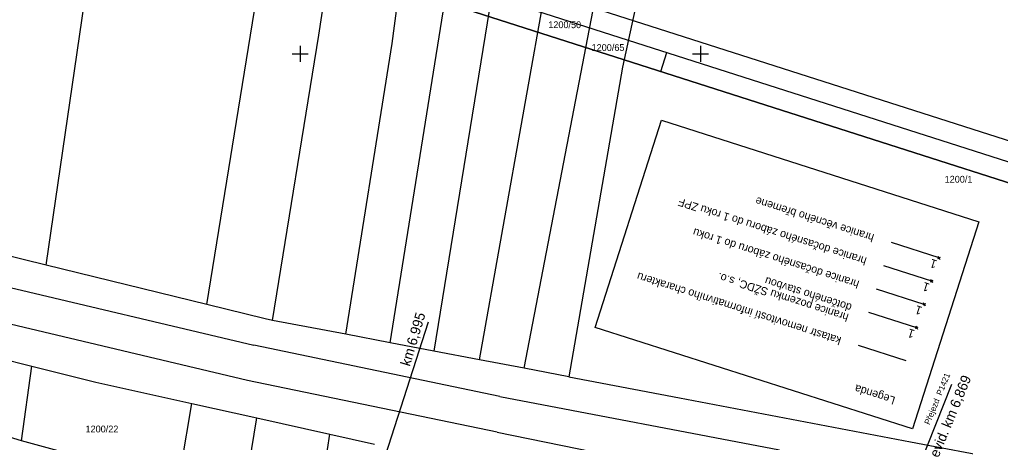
# Model space of a CAD drawing. Extents: x -779302 to -774398, y -1144902 to -1142831.
# Drawn here: x -777170.1 to -776925.1, y -1143797.2 to -1143691.5 of the extents above; entities that cross this region are included whole.
import ezdxf

# ---------------------------------------------------------------- set-up
doc = ezdxf.new("R2010")
doc.units = 0
for name, color, linetype in [('hektosit - Vrstva 5', 7, 'Continuous'), ('Hranice parcel', 7, 'Continuous'), ('legenda - Vrstva 7', 7, 'Continuous'), ('legenda I_5_2 - Vrstva 3', 7, 'Continuous'), ('Parcelní čísla', 7, 'Continuous'), ('Vnitřní kresba', 7, 'Continuous'), ('Vrstva 1', 7, 'Continuous'), ('zjednodus_g_situ-seda - Vrstva 4', 7, 'Continuous'), ('zjednodus_g_situ-seda - Vrstva 9', 7, 'Continuous')]:
    doc.layers.add(name, color=color, linetype=linetype)

msp = doc.modelspace()

# ---------------------------------------------------------------- linework, layer by layer
at = {"layer": 'hektosit - Vrstva 5'}
for p, q in [((-777102, -1143700), (-777098, -1143700)), ((-777100, -1143698), (-777100, -1143702)), ((-777002, -1143700), (-776998, -1143700)), ((-777000, -1143698), (-777000, -1143702))]:
    msp.add_line(p, q, dxfattribs=at)
at = {"layer": 'Hranice parcel'}
for p, q in [((-777163.47, -1143752.88), (-777183.19, -1143748.04)), ((-777123.33, -1143762.74), (-777163.47, -1143752.88)), ((-777088.61, -1143770.15), (-777106.91, -1143766.67)), ((-777077.49, -1143772.27), (-777088.61, -1143770.15)), ((-777187.43, -1143773.05), (-777167.09, -1143778.12)), ((-777066.64, -1143774.34), (-777077.49, -1143772.27)), ((-777055.19, -1143776.52), (-777066.64, -1143774.34)), ((-777169.67, -1143796.75), (-777167.09, -1143778.12)), ((-777044.03, -1143778.64), (-777055.19, -1143776.52)), ((-777032.87, -1143780.76), (-777044.03, -1143778.64)), ((-777130.46, -1143807.42), (-777127.12, -1143787.44)), ((-777127.12, -1143787.44), (-777110.85, -1143791.06)), ((-777169.67, -1143796.75), (-777190.45, -1143790.44)), ((-777114.23, -1143811.91), (-777110.85, -1143791.06)), ((-777110.85, -1143791.06), (-777092.58, -1143795.13)), ((-777096.09, -1143818.07), (-777092.58, -1143795.13)), ((-777092.58, -1143795.13), (-777081.42, -1143797.61)), ((-777130.46, -1143807.42), (-777169.67, -1143796.75))]:
    msp.add_line(p, q, dxfattribs=at)
for points in [[(-777123.33, -1143762.74), (-777110.9, -1143686.03), (-777093.45, -1143555.1)], [(-777106.91, -1143766.67), (-777095.36, -1143695.37), (-777073.85, -1143554.22)], [(-777163.47, -1143752.88), (-777139.64, -1143589.33), (-777135.82, -1143560)], [(-777088.61, -1143770.15), (-777077.04, -1143697.42), (-777068.9, -1143635.62), (-777059.73, -1143583.76), (-777054.08, -1143557.98)], [(-777077.49, -1143772.27), (-777044.61, -1143566.63), (-777044.04, -1143563.26)], [(-777033.04, -1143573.27), (-777033.93, -1143577.36), (-777047.95, -1143659.41), (-777066.64, -1143774.34)], [(-777055.19, -1143776.52), (-777021.75, -1143588.42), (-777021.1, -1143583.96)], [(-777044.03, -1143778.64), (-777025.1, -1143680.27), (-777016.92, -1143640), (-777009.52, -1143599.22), (-777008.49, -1143594.9)], [(-776994.01, -1143610.04), (-777008.23, -1143651.46), (-777019.5, -1143703.38), (-777032.87, -1143780.76)], [(-777106.91, -1143766.67), (-777108.78, -1143766.31), (-777123.33, -1143762.74)], [(-777167.09, -1143778.12), (-777151.05, -1143782.11), (-777127.12, -1143787.44)], [(-777032.87, -1143780.76), (-777005.26, -1143786.02), (-776947.51, -1143797.01), (-776924.63, -1143801.37), (-776885.75, -1143807.75)]]:
    msp.add_lwpolyline(points, dxfattribs=at)
at = {"layer": 'legenda - Vrstva 7'}
msp.add_lwpolyline([(-776947, -1143793.82), (-777026.29, -1143768.44), (-777009.71, -1143716.63), (-776930.42, -1143742.01)], close=True, dxfattribs=at)
at = {"layer": 'legenda I_5_2 - Vrstva 3'}
for p, q in [((-776940.36, -1143751.05), (-776952.3, -1143747.23)), ((-776940.1, -1143750.92), (-776940.73, -1143751.25)), ((-776940.61, -1143751.18), (-776939.98, -1143750.86)), ((-776940.23, -1143751.3), (-776940.55, -1143750.68)), ((-776940.48, -1143750.8), (-776940.16, -1143751.43)), ((-776940.36, -1143751.05), (-776940.36, -1143751.05)), ((-776942.22, -1143756.87), (-776954.16, -1143753.04)), ((-776944.08, -1143762.68), (-776956.03, -1143758.86)), ((-776941.96, -1143756.74), (-776942.59, -1143757.06)), ((-776942.47, -1143757), (-776941.84, -1143756.67)), ((-776942.09, -1143757.12), (-776942.41, -1143756.49)), ((-776942.35, -1143756.62), (-776942.02, -1143757.24)), ((-776942.22, -1143756.87), (-776942.22, -1143756.87)), ((-776943.83, -1143762.55), (-776944.45, -1143762.88)), ((-776944.33, -1143762.81), (-776943.7, -1143762.49)), ((-776943.95, -1143762.93), (-776944.27, -1143762.3)), ((-776944.21, -1143762.43), (-776943.88, -1143763.06)), ((-776944.08, -1143762.68), (-776944.08, -1143762.68)), ((-776945.94, -1143768.5), (-776957.89, -1143764.67)), ((-776945.69, -1143768.37), (-776946.31, -1143768.69)), ((-776946.19, -1143768.62), (-776945.56, -1143768.3)), ((-776945.81, -1143768.75), (-776946.13, -1143768.12)), ((-776946.07, -1143768.24), (-776945.74, -1143768.87)), ((-776945.94, -1143768.5), (-776945.94, -1143768.5)), ((-776948.59, -1143776.77), (-776960.54, -1143772.95))]:
    msp.add_line(p, q, dxfattribs=at)
at = {"layer": 'Vnitřní kresba'}
for p, q in [((-777312.68, -1143725.18), (-777111.56, -1143772.88)), ((-777113.15, -1143781.74), (-777316.11, -1143733.54)), ((-777050.15, -1143785.67), (-777111.56, -1143772.88)), ((-777050.79, -1143794.65), (-777113.15, -1143781.74)), ((-777050.15, -1143785.67), (-776980.28, -1143799.08)), ((-777050.79, -1143794.65), (-776981.09, -1143808.78))]:
    msp.add_line(p, q, dxfattribs=at)
at = {"layer": 'Vrstva 1'}
msp.add_line((-777009.93, -1143704.44), (-777008.41, -1143699.68), dxfattribs=at)
for points in [[(-776606.88, -1143822.95), (-777806.9, -1143438.86), (-777897.43, -1143721.71), (-776697.42, -1144105.81)], [(-776700.65, -1144099.52), (-777891.15, -1143718.47), (-777803.66, -1143445.14), (-776613.17, -1143826.19)], [(-776619.45, -1143829.42), (-777605.19, -1143513.91), (-777689.63, -1143777.73), (-776703.89, -1144093.24)], [(-776703.89, -1144093.24), (-777689.63, -1143777.73), (-777605.19, -1143513.91), (-776619.45, -1143829.42)]]:
    msp.add_lwpolyline(points, close=True, dxfattribs=at)
at = {"layer": 'zjednodus_g_situ-seda - Vrstva 4'}
msp.add_line((-776971.31, -1143868.72), (-776937.22, -1143782.62), dxfattribs=at)
at = {"layer": 'zjednodus_g_situ-seda - Vrstva 9'}
msp.add_line((-777086.17, -1143823.78), (-777067.91, -1143767.04), dxfattribs=at)

# ---------------------------------------------------------------- texts
at = {"layer": 'legenda I_5_2 - Vrstva 3'}
for s, height, p in [('hranice dočasného záboru do 1 roku ZPF', 2, (-776958.3, -1143751.03)), ('hranice věcného břemene', 2, (-776956.44, -1143745.21)), ('hranice dočasného záboru do 1 roku', 2, (-776960.16, -1143756.84)), ('1', 2.16, (-776940.7, -1143751.75)), ('katastr nemovitostí informativního charakteru', 2, (-776964.67, -1143770.93)), ('hranice pozemku SŽDC, s.o.', 2, (-776962.81, -1143765.12)), ('dotčeného stavbou', 2, (-776962.02, -1143762.66)), ('1', 2.16, (-776942.56, -1143757.56)), ('1', 2.16, (-776944.42, -1143763.38)), ('1', 2.16, (-776946.28, -1143769.19)), ('Legenda', 2, (-776951.17, -1143785.88))]:
    msp.add_text(s, height=height, rotation=162.2529, dxfattribs=at).set_placement(p)
at = {"layer": 'Parcelní čísla'}
for s, p in [('1200/50', (-777038.03, -1143693.62)), ('1200/65', (-777027.2, -1143699.32)), ('1200/1', (-776938.99, -1143732.24)), ('1200/22', (-777153.65, -1143794.68))]:
    msp.add_text(s, height=1.7, dxfattribs=at).set_placement(p)
at = {"layer": 'zjednodus_g_situ-seda - Vrstva 4'}
for s, height, p in [('Přejezd  P1421', 1.5, (-776942.75, -1143792.9)), ('evid. km 6,869', 2.5, (-776940.55, -1143801.16))]:
    msp.add_text(s, height=height, rotation=67.6334, dxfattribs=at).set_placement(p)
at = {"layer": 'zjednodus_g_situ-seda - Vrstva 9'}
msp.add_text('km 6,995', height=2.5, rotation=73.2741, dxfattribs=at).set_placement((-777072.61, -1143778.31))

doc.saveas('drawing.dxf')
